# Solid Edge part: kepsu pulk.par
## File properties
Author: Türk
Template: Iso Part.par
Last saved by: Türk
Revision: 2
Application: Solid Edge
Accuracy: 0,990
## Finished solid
Body 1: solid body, 8 faces, 8 edges, 0 vertices.
  Faces by surface: cone 4, cylinder 2, plane 2
  Edges by curve: circle 8
Bounding box of the edges (mm): 20.000 x 40.000 x 20.000, from (-10, 0, -10) to (10, 40, 10).
Cylindrical faces by radius (mm): R5 x1, R10 x1
Conical faces (half-angle, radius in mm at the cone's reference point): 45 deg R5 x1, 45 deg R5.5 x1, 45 deg R9.5 x1, 45 deg R10 x1
Planar faces by outward normal: +y 1, -y 1
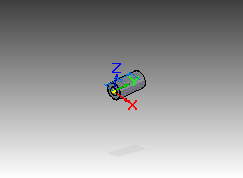
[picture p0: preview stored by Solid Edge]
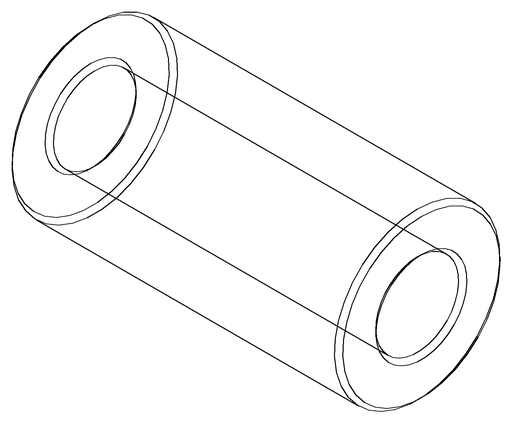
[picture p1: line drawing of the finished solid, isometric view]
